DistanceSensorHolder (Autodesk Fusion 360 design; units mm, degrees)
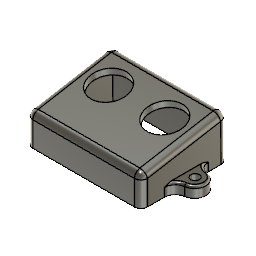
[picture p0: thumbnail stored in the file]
parameter "DistanceEntreCapteur10mm" = 10
parameter "DiametreCapteur16mm" = 16
parameter "LargeurPBC46mm" = 46
parameter "LongueurPBCAvecPin35mm" = 35
parameter "HauteurPBC19mm" = 19
parameter "LongueurPBC21mm" = 21
sketch "Sketch1" plane through (0, 0, 0) normal (1, 0, 0) x axis (0, 1, 0)
  line L1 (20, 14) -> (20, 0)
  line L2 (60, 0) -> (20, 0)
  line L3 (59.838, 20.9391) -> (20, 14)
  line L4 (60, 0) -> (59.838, 20.9391)
extrude "Extrude1" new body sketch "Sketch1" along normal blind 53 (= "LargeurPBC46mm + 7 mm")
shell "Shell1" innerThickness 3
sketch "Sketch2" plane through (0, -1.7778, 10.2067) normal (0, -0.1716, 0.9852) x axis (1, 0, 0)
  line L1 (0, 22.1057) -> (0, 62.5436)
  line L2 (53, 22.1057) -> (0, 22.1057)
  line L3 (53, 62.5436) -> (53, 22.1057)
  line L4 (0, 62.5436) -> (53, 62.5436)
  line L5 (23.7727, 52.0436) -> (23.7727, 62.5436)
  line L6 (26.5, 52.0436) -> (26.5, 55.0363)
  line L7 (31.5, 52.0436) -> (26.5, 52.0436)
  line L8 (21.5, 52.0436) -> (26.5, 52.0436)
  circle C1 centre (39.5, 48.4837) radius 8.25
  circle C2 centre (13.5, 48.4837) radius 8.25
  point P6 (23.7727, 62.5436)
  point P9 (26.5, 52.0436)
  point P10 (31.5, 52.0436)
  coincident L4 P6
  perpendicular L4 L5
  perpendicular L6 L7
  perpendicular L5 L8
  dimension "d15" distance P9 P10 = 5 (= "DistanceEntreCapteur10mm / 2")
sketch "Sketch4" plane through (0, 0, 0) normal (0, 0, -1) x axis (1, 0, 0)
  line L1 (3, -56.9999) -> (50, -56.9999)
  line L2 (3, -23) -> (3, -56.9999)
  line L3 (50, -23) -> (3, -23)
  line L4 (50, -56.9999) -> (50, -23)
  line L5 (0, -60) -> (0, -20)
  line L6 (53, -60) -> (0, -60)
  line L7 (53, -20) -> (53, -60)
  line L8 (0, -20) -> (53, -20)
  line L9 (1, -43) -> (1, -39)
  line L10 (52, -43) -> (52, -39)
  circle C1 centre (-4, -41) radius 2
  circle C2 centre (57, -41) radius 2
  arc A1 centre (-3.2778, -41) radius 4.7222 clockwise from (1, -43) to (1, -39)
  arc A2 centre (56.8, -41) radius 5.2 clockwise from (52, -39) to (52, -43)
  perpendicular L3 L9
  parallel L7 L10
extrude "Extrude3" add sketch "Sketch4" profile of L5 L7 C1 C2 A1 A2 against normal blind 5
sketch "Sketch5" plane through (0, -1.7778, 10.2067) normal (0, -0.1716, 0.9852) x axis (1, 0, 0)
  line L1 (0, 22.1057) -> (0, 62.5436)
  line L2 (53, 22.1057) -> (0, 22.1057)
  line L3 (53, 62.5436) -> (53, 22.1057)
  line L4 (0, 62.5436) -> (53, 62.5436)
  line L5 (53, 47) -> (25.2681, 47)
  line L6 (0, 47) -> (25.2681, 47)
  line L7 (26.5, 47) -> (26.5, 52.3639)
  line L8 (31.5, 47) -> (26.5, 47)
  line L9 (21.5, 47) -> (26.5, 47)
  line L10 (39.5, 47) -> (31.5, 47)
  line L11 (13.5, 47) -> (21.5, 47)
  circle C1 centre (13.5, 47) radius 8.25
  circle C2 centre (39.5, 47) radius 8.25
  point P7 (53, 47)
  point P10 (26.5, 47)
  point P14 (13.5, 47)
  point P15 (13.5, 47)
  point P13 (39.5, 47)
  point P16 (39.5, 47)
  point P11 (31.5, 47)
  point P12 (21.5, 47)
  coincident L3 P7
  perpendicular L3 L5
  coincident L5 P10
  perpendicular L5 L7
  perpendicular L7 L8
  perpendicular L7 L9
  parallel L5 L10
  parallel L6 L11
  coincident P14 P15
  coincident P13 P16
  dimension "d28" distance P10 P11 = 5 (= "DistanceEntreCapteur10mm / 2")
  dimension "d29" distance P10 P12 = 5 (= "DistanceEntreCapteur10mm / 2")
  dimension "d31" distance P11 P13 = 8 (= "DiametreCapteur16mm / 2")
  dimension "d32" distance P12 P14 = 8 (= "DiametreCapteur16mm / 2")
  dimension "d33" diameter C1 = 16.5 (= "DiametreCapteur16mm + 0.5 mm")
  dimension "d34" diameter C2 = 16.5 (= "DiametreCapteur16mm + 0.5 mm")
extrude "Extrude4" cut sketch "Sketch5" profile of L5 L6 L8 L9 L10 L11 C1 C2 against normal blind 3
fillet "Fillet1" radius 3
fillet "Fillet2" radius 3
fillet "Fillet3" radius 3
fillet "Fillet4" radius 3
fillet "Fillet5" radius 5
fillet "Fillet6" radius 5
fillet "Fillet7" radius 5
fillet "Fillet8" radius 5
fillet "Fillet9" radius 1
fillet "Fillet10" radius 1
extrude "Extrude2" cut sketch "Sketch2" profile of C1 C2 against normal blind 3
sketch "Sketch3" plane through (0, 0, 0) normal (0, 0, -1) x axis (1, 0, 0)
  line L1 (3, -56.9999) -> (50, -56.9999)
  line L2 (3, -23) -> (3, -56.9999)
  line L3 (50, -23) -> (3, -23)
  line L4 (50, -56.9999) -> (50, -23)
  line L5 (0, -31.4315) -> (0, -23)
  line L6 (50, -60) -> (3, -60)
  line L7 (53, -51.1292) -> (53, -56.9999)
  line L8 (3, -20) -> (50, -20)
  line L9 (53, -23) -> (53, -30.8708)
  line L10 (0, -56.9999) -> (0, -50.5685)
  circle C1 centre (-3.8235, -39.953) radius 2
  arc A1 centre (-4.0845, -39.953) radius 5.0027 between (-8.7235, -41.8253) and (-8.7235, -38.0806)
  circle C2 centre (-3.8235, -39.953) radius 2
  arc A2 centre (-4.0845, -39.953) radius 5.0027 between (-8.7235, -41.8253) and (-8.7235, -38.0806)
  circle C3 centre (57, -41) radius 2
  circle C4 centre (-4, -41) radius 2
  arc A3 centre (-3.2778, -41) radius 4.7222 clockwise from (-4.1143, -45.6475) to (-4.1143, -36.3525)
  arc A4 centre (56.8, -41) radius 5.2 clockwise from (57.4118, -35.8361) to (57.4118, -46.1639)
  closed curve K1 centre (50, -56.9999)
  arc A5 centre (58, -51.1292) radius 5 clockwise from (53, -51.1292) to (57.4118, -46.1639)
  arc A6 centre (58, -30.8708) radius 5 clockwise from (57.4118, -35.8361) to (53, -30.8708)
  arc A7 centre (50, -23) radius 3 clockwise from (50, -20) to (53, -23)
  arc A8 centre (3, -23) radius 3 clockwise from (0, -23) to (3, -20)
  arc A9 centre (-5, -31.4315) radius 5 clockwise from (0, -31.4315) to (-4.1143, -36.3525)
  arc A10 centre (-5, -50.5685) radius 5 clockwise from (-4.1143, -45.6475) to (0, -50.5685)
  closed curve K2 centre (3, -56.9999)
  dimension "d23" diameter C1 = 4
  dimension "d24" diameter C2 = 4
